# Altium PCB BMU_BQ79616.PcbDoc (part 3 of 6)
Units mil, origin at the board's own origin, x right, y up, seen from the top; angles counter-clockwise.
Board outline 7605 x 4005 mil, 4 copper layers (Top Layer, Layer 1, Layer 2, Bottom Layer), stack 37.446 mil thick; 709 components, 447 nets, 2028 pads, 1862 vias.
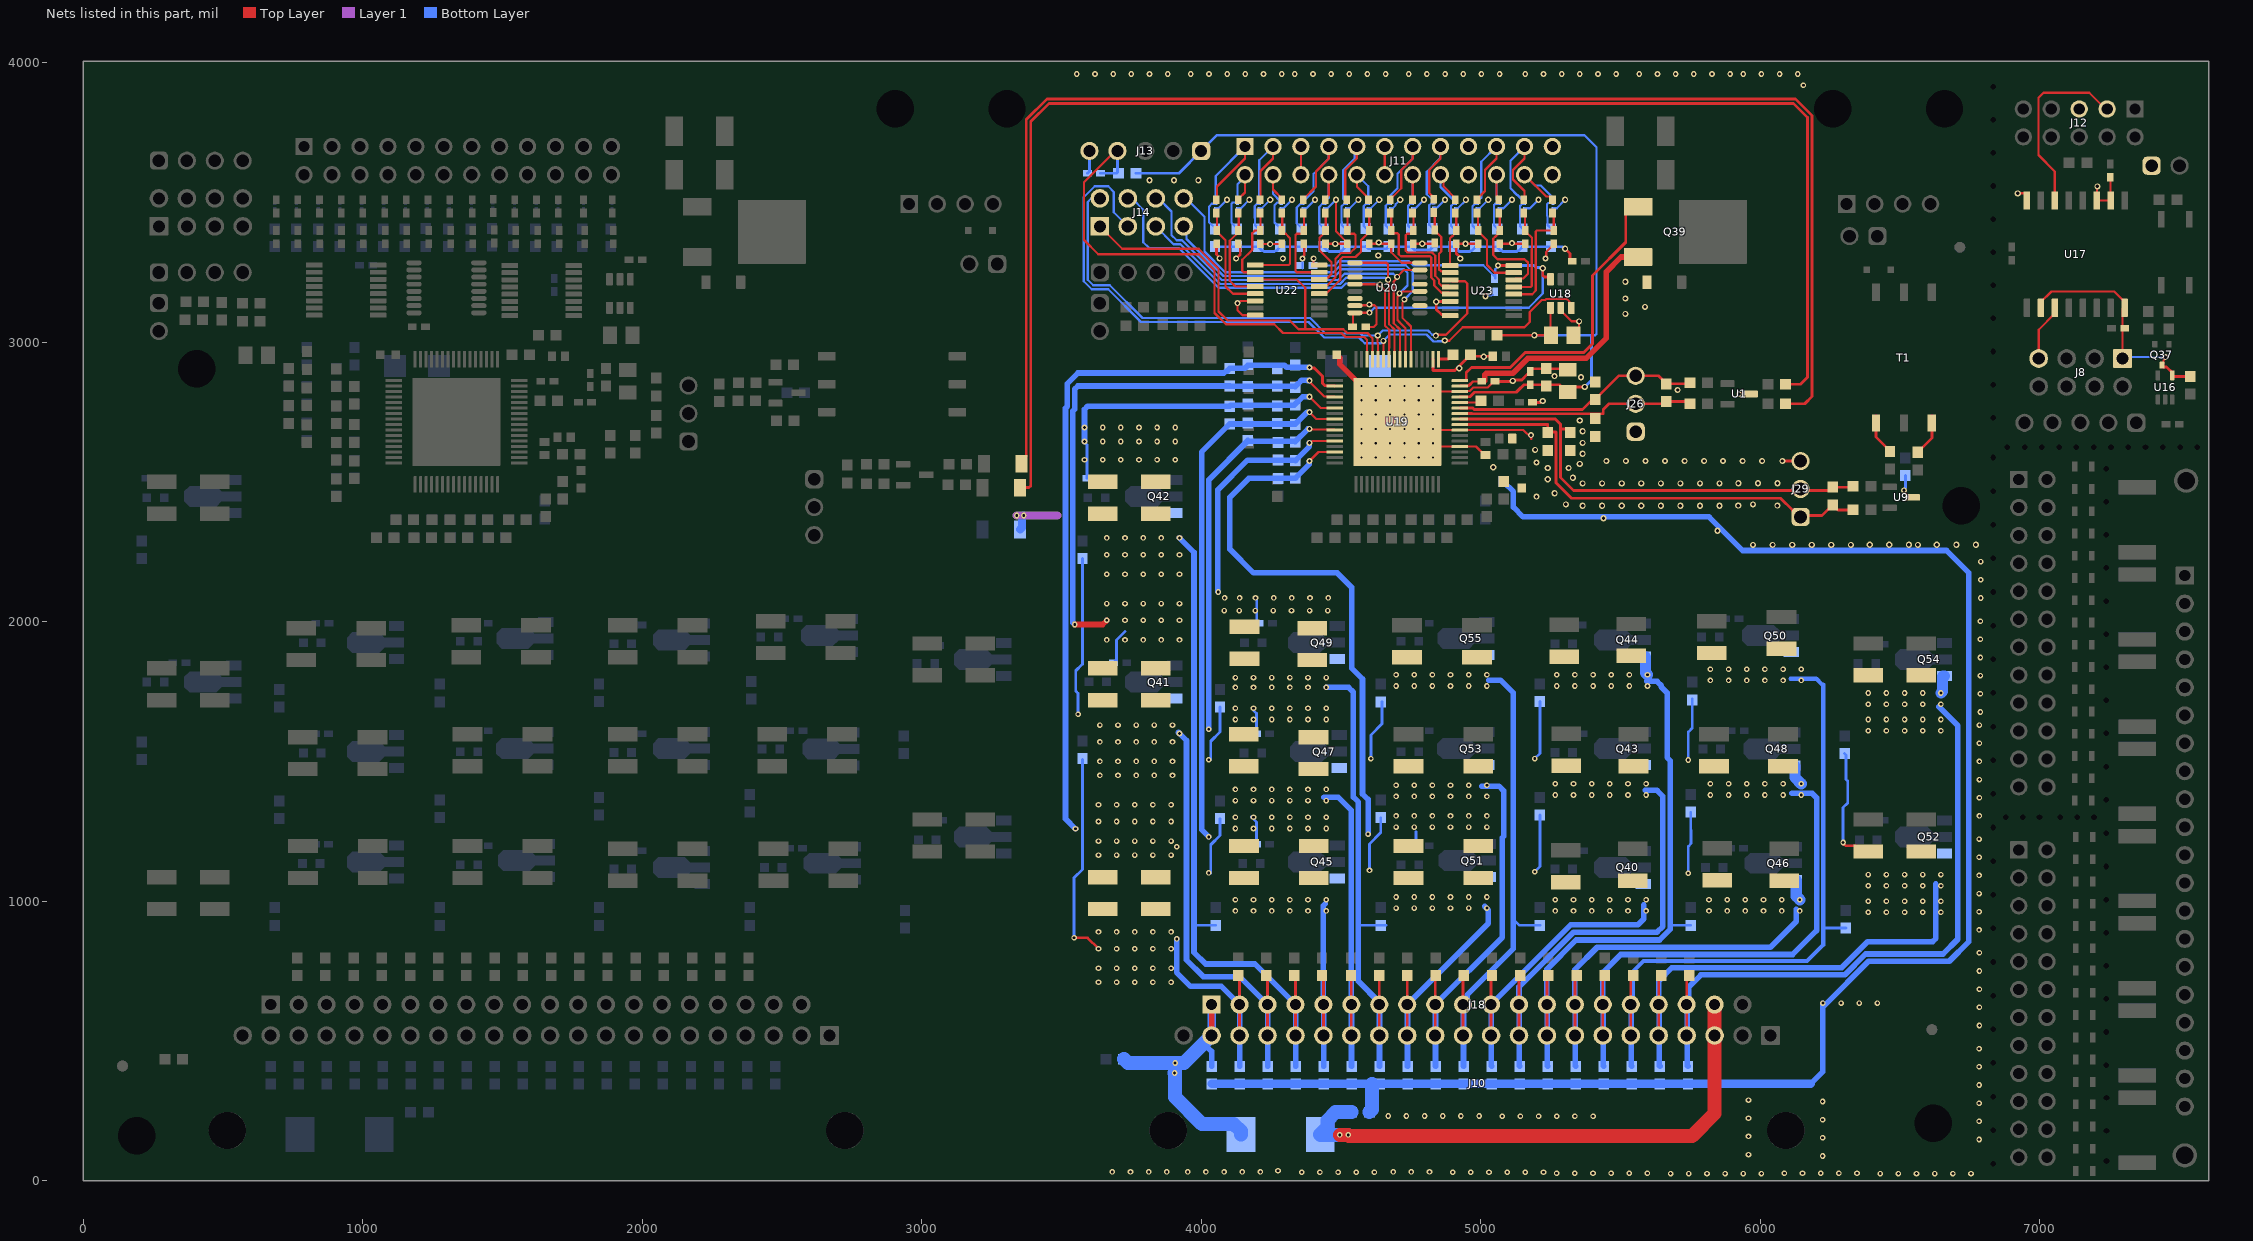
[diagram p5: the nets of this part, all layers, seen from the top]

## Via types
v1: diameter 20, hole 10, Top Layer to Bottom Layer, tented both sides, 1385 vias
v2: diameter 22.01, hole 12.01, Top Layer to Bottom Layer, tented both sides, 405 vias
v3: diameter 19.68, hole 7.87, Top Layer to Bottom Layer, 72 vias

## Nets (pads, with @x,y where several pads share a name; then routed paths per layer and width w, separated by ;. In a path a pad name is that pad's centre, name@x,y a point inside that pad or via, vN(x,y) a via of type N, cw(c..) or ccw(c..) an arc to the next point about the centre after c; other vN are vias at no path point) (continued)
A1_CB10: C212.2 C216.1 R478.1 R480.2 R481.2 U19.14 | length 2085.4
  Top Layer w8: v2(4387.36,2575) 4419.69,2607.32 U19.14@4477.36,2607.32
  Bottom Layer w10: R478.1@4768.74,1198.54 4768.74,1248.62
  Bottom Layer w20: v2(4387.36,2575) 4386.98,2574.62 4386.98,2564.1 4337.36,2514.49 C212.2@4337.36,2513.5 4337.11,2513.25 4272.03,2513.25 4271.77,2512.99 4170.35,2512.99 4102.36,2445 4102.36,2260 4187.36,2175 4486.9,2175 4538.61,2123.28 4538.61,1833.75 4577.36,1795 4577.36,1383.5 4595.86,1365 4597.36,1365 v1(4597.36,1240)
  other v1: 4697.36,1265 4762.36,1265 4827.36,1265 4892.36,1265 4957.36,1265 5022.36,1265 4697.36,1305 4762.36,1305 4827.36,1305 4892.36,1305 4957.36,1305 5022.36,1305
A1_CB11: C208.2 C212.1 R468.1 R470.2 R471.2 U19.12 | length 959.1
  Top Layer w8: v2(4387.36,2640) 4391.15,2640 4397.85,2646.69 U19.12@4477.36,2646.69
  Bottom Layer w10: v1@4194.41,2086.25 4194.41,2083.54 4198.74,2079.21 R468.1@4198.74,1995
  Bottom Layer w20: v1(4060.86,2106.5) 4059.36,2108 4059.36,2472 4165.87,2578.5 4271.77,2578.5 4272.78,2577.5 4336.36,2577.5 C212.1@4337.36,2576.5 4337.36,2577.48 4386.98,2627.1 4386.98,2639.62 v2(4387.36,2640)
  other v1: 4082.36,2040 4136.07,2040 4193.12,2040 4258.12,2040 4323.12,2040 4388.12,2040 4453.12,2040 4083.65,2085.35 4137.36,2085.35 4194.41,2085.35 4259.41,2085.35 4324.41,2085.35 4389.41,2085.35 4454.41,2085.35
A1_CB12: C204.2 C208.1 R87.2 R458.1 R460.2 R461.2 U19.10 | length 1515.8
  Top Layer w8: v2(4387.36,2690) 4389.39,2687.97 4475.46,2687.97 U19.10@4477.36,2686.06
  Bottom Layer w10: v1@4187.36,1685 4187.36,1682.29 4197.52,1672.14 R458.1@4197.52,1598.76
  Bottom Layer w20: v1(4027.36,1615) 4027.36,2508.11 4166.77,2647.52 R87.2@4166.77,2648.5 4169.27,2646 4334.27,2646 C204.2@4336.77,2643.5 4336.77,2644.49 4381.9,2689.62 4386.98,2689.62 v2(4387.36,2690)
  other v1: 4122.36,1650 4187.36,1650 4252.36,1650 4317.36,1650 4382.36,1650 4447.36,1650 4122.36,1690 4187.36,1690 4252.36,1690 4317.36,1690 4382.36,1690 4447.36,1690
A1_CB13: C199.2 C204.1 R87.1 R92.2 R448.1 R449.2 R450.2 U19.8 | length 2041
  Top Layer w8: v2(4387.36,2750) 4411.93,2725.43 U19.8@4477.36,2725.43
  Bottom Layer w10: v1@4179.41,1301.25 4197.52,1283.14 R448.1@4197.52,1203.76
  Bottom Layer w20: v1(4027.36,1230) 4001.36,1256 4001.36,2607.11 4101.77,2707.52 4101.77,2708.5 4102.78,2707.5 4335.77,2707.5 C204.1@4336.77,2706.5 4336.77,2707.48 4378.91,2749.62 4386.98,2749.62 v2(4387.36,2750)
  other v1: 4122.36,1260 4187.36,1260 4252.36,1260 4317.36,1260 4382.36,1260 4447.36,1260 4122.36,1300 4187.36,1300 4252.36,1300 4317.36,1300 4382.36,1300 4447.36,1300
A1_CB14: C194.2 C199.1 R92.1 R150.2 R437.1 R439.2 R440.2 U19.6 | length 1180.8
  Top Layer w8: v2(4387.36,2805) 4427.56,2764.8 U19.6@4477.36,2764.8
  Bottom Layer w10: v1(3582.36,2645) 3582.36,2642.29 3591.69,2632.97 R437.1@3591.69,2513.75
  Bottom Layer w20: v1(3582.36,2645) 3582.36,2759.78 3594.08,2771.5 4101.77,2771.5 4105.28,2775 4333.27,2775 4336.77,2778.5 4336.77,2779.49 4345.47,2788.19 4346.46,2788.19 4362.88,2804.62 4386.98,2804.62 v2(4387.36,2805)
  other v1: 3582.36,2580 3647.36,2580 3712.36,2580 3777.36,2580 3842.36,2580 3907.36,2580 3647.36,2645 3712.36,2645 3777.36,2645 3842.36,2645 3907.36,2645 3582.36,2695 3647.36,2695 3712.36,2695 3777.36,2695 3842.36,2695 3907.36,2695
A1_CB15: C191.2 C194.1 R150.1 R154.2 R428.1 R429.2 R432.2 U19.4 | length 2072.7
  Top Layer w8: v2(4387.36,2863) 4390.04,2860.32 4390.04,2856.31 4440.27,2806.08 4475.46,2806.08 U19.4@4477.36,2804.17
  Top Layer w20: v1(3547.36,1990) 3647.36,1990 v1(3662.36,2005)
  Bottom Layer w10: R428.1@3686.69,1853.75 3692.36,1859.43 3696.3,1859.43 3697.44,1860.57 3697.44,1935.07 3727.36,1965
  Bottom Layer w20: v1(3547.36,1990) 3540.31,1997.05 3540.31,2753.28 3547,2759.97 3547,2831.79 3558.72,2843.5 R154.2@4101.77,2843.5 4102.78,2842.5 4166.77,2842.5 4335.77,2842.5 4336.77,2841.5 4336.77,2842.48 4345.47,2851.18 4346.46,2851.18 4359.89,2864.62 4380.47,2864.62 4381.71,2863.38 4386.98,2863.38 v2(4387.36,2863)
  other v1: 3662.36,1935 3727.36,1935 3792.36,1935 3857.36,1935 3922.36,1935 3727.36,2005 3792.36,2005 3857.36,2005 3922.36,2005 3662.36,2065 3727.36,2065 3792.36,2065 3857.36,2065 3922.36,2065
A1_CB16: C162.1 C191.1 R154.1 R188.2 R420.2 R422.2 U19.2 | length 2641.8
  Top Layer w10: v2(4387.36,2910) 4389.66,2907.7 4404.66,2907.7 4433.87,2878.49 4433.87,2853.49 4442.91,2844.45 4476.46,2844.45 U19.2@4477.36,2843.54
  Bottom Layer w20: v1(3550.31,1258.75) 3514.31,1294.75 3514.31,2764.05 3521,2770.74 3521,2852.2 3558.8,2890 4081.36,2890 4088.17,2896.81 4093.07,2896.81 4101.77,2905.51 R154.1@4101.77,2906.5 4155.75,2906.5 4166.77,2917.52 4166.77,2918.5 4297.36,2918.5 4305.87,2910 v2(4387.36,2910)
  other v1: 3632.36,1165 3697.36,1165 3762.36,1165 3827.36,1165 3892.36,1165 3912.36,1195 3632.36,1215 3697.36,1215 3762.36,1215 3827.36,1215 3892.36,1215 3632.36,1285 3697.36,1285 3762.36,1285 3827.36,1285 3892.36,1285 3632.36,1345 3697.36,1345 3762.36,1345 3827.36,1345 3892.36,1345
A1_CELL0: C103.1 D56.2 J10.3 J18.19 R418.2 | length 2245.1
  Top Layer w50: v1@4496.19,163.41 v1(4526.01,163.41) ; v1@4529.41,160 5757.36,160 5837.36,240 J10.3@5837.36,519.29 J18.19@5837.36,630
  Bottom Layer w20: D56.2@4425.83,165 D56.2@4427.42,163.41 ; J18.19@5837.36,630 5839.86,627.5 5839.86,411.36 C103.1@5842.36,408.86
  Bottom Layer w50: D56.2@4425.83,165 4452.01,191.18 4452.01,215.71 4481.3,245 R418.2@4538.5,245 ; D56.2@4427.42,163.41 v1(4526.01,163.41)
  other v1: 4496.01,163.41
A1_CELL0S: C104.1 J10.4 J18.18 Q54.3 R499.1 R500.1 R501.1 | length 2459.7
  Top Layer w10: J10.4@5737.36,519.29 J18.18@5737.36,630 R501.1@5737.36,723.5
  Bottom Layer w15: J10.4@5737.36,519.29 J10.4@5739.72,521.65
  Bottom Layer w20: C104.1@5742.08,408.86 5739.72,411.22 5739.72,521.65 5739.72,627.64 J18.18@5737.36,630 5744.84,637.48 5744.84,692.48 5788.36,736 6303.06,736 6378.06,811 6654.58,811 6707.36,863.79 6707.36,1628.3 6639.41,1696.25
  Bottom Layer w40: v1(6647.36,1745) 6652.68,1750.31 6652.68,1803.66 6654.96,1805.94 Q54.3@6660.24,1805.94
  other v1: 6387.36,1610 6452.36,1610 6517.36,1610 6582.36,1610 6647.36,1610 6387.36,1650 6452.36,1650 6517.36,1650 6582.36,1650 6647.36,1650 6387.36,1705 6452.36,1705 6517.36,1705 6582.36,1705 6647.36,1705 6387.36,1745 6452.36,1745 6517.36,1745 6582.36,1745
A1_CELL1: C105.1 J10.5 J18.17 Q52.3 R489.1 R492.1 R493.1 R495.1 | length 2180.8
  Top Layer w10: J10.5@5637.36,519.29 J18.17@5637.36,630 R493.1@5637.36,724.44 ; v1(6297.36,1210) 6299.28,1208.09 6299.28,1203.1 6302.36,1203.1 6306.96,1198.5 6341.77,1198.5 R489.1@6367.36,1172.91
  Bottom Layer w10: v1(6297.36,1210) 6297.36,1335 6313.72,1351.36 6313.72,1429.38 6307.36,1435.74 6307.36,1523.5 R495.1@6302.36,1528.5
  Bottom Layer w20: C105.1@5641.81,408.86 5639.58,411.08 5639.58,627.78 J18.17@5637.36,630 5637.36,715 5684.36,762 6292.29,762 6385.29,855 6617.7,855 6629.41,866.72 6629.41,1061.25
  other v1: 6387.36,960 6452.36,960 6517.36,960 6582.36,960 6647.36,960 6387.36,1000 6452.36,1000 6517.36,1000 6582.36,1000 6647.36,1000 6387.36,1055 6452.36,1055 6517.36,1055 6582.36,1055 6647.36,1055 6387.36,1095 6452.36,1095 6517.36,1095 6582.36,1095 6647.36,1095
A1_CELL2: C106.1 J10.6 J18.16 Q50.3 R479.1 R482.1 R483.1 R485.1 | length 2412
  Top Layer w10: J10.6@5537.36,519.29 J18.16@5537.36,630 R483.1@5537.36,725.38
  Bottom Layer w10: 6225.86,910.38 6232.74,903.5 R485.1@6307.36,903.5
  Bottom Layer w15: J10.6@5537.36,519.29 5539.45,521.37 J10.6@5540.06,521.99 ; J18.16@5545.06,630 5545.06,747.7 5582.86,785.5 6167.86,785.5 6225.86,843.5 6225.86,910.38 6225.86,1775 6222.36,1775 6201.12,1796.25 6109.41,1796.25
  Bottom Layer w20: J18.16@5537.36,630 5539.45,627.92 5539.45,521.37 5539.45,410.94 C106.1@5541.53,408.86
  other v1: 5822.36,1790 5887.36,1790 5952.36,1790 6017.36,1790 6082.36,1790 6147.36,1790 5822.36,1830 5887.36,1830 5952.36,1830 6017.36,1830 6082.36,1830 6147.36,1830
A1_CELL3: C107.1 J10.7 J18.15 Q48.3 R469.1 R472.1 R473.1 R475.1 | length 2247.4
  Top Layer w10: J10.7@5437.36,519.29 J18.15@5437.36,630 R473.1@5437.36,726.32
  Bottom Layer w10: v1(5743.36,1505) 5743.36,1606 5757.36,1620 R475.1@5757.36,1723.5
  Bottom Layer w20: C107.1@5441.25,408.86 5439.31,410.8 5439.31,628.06 J18.15@5437.36,630 5437.36,745 5501.36,809 6116.36,809 6202.36,895 6202.36,1370 6186.12,1386.25 6114.41,1386.25
  Bottom Layer w40: Q48.3@6117.17,1485.94 6122.44,1485.94 6124.72,1483.66 6124.72,1442.64 v1(6147.36,1420)
  other v1: 5822.36,1380 5887.36,1380 5952.36,1380 6017.36,1380 6082.36,1380 6147.36,1380 5822.36,1420 5887.36,1420 5952.36,1420 6017.36,1420 6082.36,1420
A1_CELL4: C108.1 J10.8 J18.14 Q46.3 R459.1 R462.1 R463.1 R465.1 | length 1769.2
  Top Layer w10: J10.8@5337.36,519.29 J18.14@5337.36,630 R463.1@5337.36,727.25
  Bottom Layer w10: v1(5743.36,1100) 5743.36,1196 5753.36,1206 5753.36,1254.56 5752.36,1255.56 R465.1@5752.36,1318.5
  Bottom Layer w20: C108.1@5340.97,408.86 5339.17,410.66 5339.17,628.19 J18.14@5337.36,630 5337.36,755 5417.36,835 6037.36,835 6129.41,927.05 6129.41,971.25
  Bottom Layer w40: Q46.3@6122.17,1076.57 6127.44,1076.57 6129.72,1074.28 6129.72,1017.64 v1(6142.36,1005)
  other v1: 5817.36,965 5882.36,965 5947.36,965 6012.36,965 6077.36,965 6142.36,965 5817.36,1005 5882.36,1005 5947.36,1005 6012.36,1005 6077.36,1005
A1_CELL5: C109.1 J10.9 J18.13 Q44.3 R451.1 R452.1 R453.1 R455.1 | length 2151.7
  Top Layer w10: J10.9@5237.36,519.29 J18.13@5237.36,630 R453.1@5237.36,728.19
  Bottom Layer w10: 5678.36,915 5679.86,913.5 R455.1@5752.36,913.5
  Bottom Layer w20: C109.1@5240.69,408.86 5239.03,410.52 5239.03,628.33 J18.13@5237.36,630 5237.36,756.46 5341.9,861 5640.13,861 5678.36,899.23 5678.36,915 5678.36,1503.09 5667.36,1514.09 5667.36,1745.78 5646.36,1766.78 5646.36,1771.78 5631.9,1786.25 5594.41,1786.25
  Bottom Layer w40: Q44.3@5582.17,1875.94 5587.44,1875.94 5589.72,1873.66 5589.72,1817.64 v1(5597.36,1810)
  other v1: 5272.36,1770 5337.36,1770 5402.36,1770 5467.36,1770 5532.36,1770 5597.36,1770 5272.36,1810 5337.36,1810 5402.36,1810 5467.36,1810 5532.36,1810
A1_CELL6: C110.1 J10.10 J18.12 Q43.3 R441.1 R442.1 R443.1 R445.1 | length 1849.9
  Top Layer w10: J10.10@5137.36,519.29 J18.12@5137.36,630 R443.1@5137.36,729.13
  Bottom Layer w10: v1(5193.36,1510) 5212.36,1529 R445.1@5212.36,1715
  Bottom Layer w20: C110.1@5140.42,408.86 5138.89,410.39 5138.89,519.29 5138.89,628.47 J18.12@5137.36,630 5137.36,693.23 5333.13,889 5631.36,889 5652.36,910 5652.36,1375 5631.12,1396.25 5589.41,1396.25
  other v1: 5267.36,1380 5332.36,1380 5397.36,1380 5462.36,1380 5527.36,1380 5592.36,1380 5267.36,1420 5332.36,1420 5397.36,1420 5462.36,1420 5527.36,1420 5592.36,1420
A1_CELL7: C111.1 J10.11 J18.11 Q40.3 R430.1 R431.1 R433.1 R435.1 | length 1367.9
  Top Layer w10: J10.11@5037.36,519.29 J18.11@5037.36,630 R433.1@5037.36,730.07
  Bottom Layer w10: v1(5193.36,1105) 5212.36,1124 R435.1@5212.36,1308.5
  Bottom Layer w20: C111.1@5040.14,408.86 5038.75,410.25 5038.75,628.61 J18.11@5037.36,630 5322.36,915 5562.36,915 5584.41,937.05 5584.41,986.25
  other v1: 5267.36,965 5332.36,965 5397.36,965 5462.36,965 5527.36,965 5592.36,965 5267.36,1005 5332.36,1005 5397.36,1005 5462.36,1005 5527.36,1005 5592.36,1005
A1_CELL8: C112.1 J10.12 J18.10 Q55.3 R419.1 R421.1 R423.1 R425.1 | length 1835
  Top Layer w10: J10.12@4937.36,519.29 J18.10@4937.36,630 R423.1@4937.36,731
  Bottom Layer w10: 5116.36,936 5138.86,913.5 R425.1@5212.36,913.5
  Bottom Layer w20: C112.1@4939.86,408.86 4938.61,410.11 4938.61,519.29 4938.61,628.75 J18.10@4937.36,630 4937.36,642.17 4951.54,656.35 4951.54,664.18 5116.36,829 5116.36,936 5116.36,1746 5071.12,1791.25 5029.41,1791.25
  other v1: 4697.36,1770 4762.36,1770 4827.36,1770 4892.36,1770 4957.36,1770 5022.36,1770 4697.36,1810 4762.36,1810 4827.36,1810 4892.36,1810 4957.36,1810 5022.36,1810
A1_CELL9: C113.1 J10.13 J18.9 Q53.3 R490.1 R491.1 R494.1 R496.1 | length 1607.2
  Top Layer w10: J10.13@4837.36,519.29 J18.9@4837.36,630 R494.1@4837.36,731.94
  Bottom Layer w10: v1(4607.36,1510) 4607.36,1595 4647.36,1635 R496.1@4647.36,1713.5
  Bottom Layer w20: C113.1@4839.58,408.86 4838.47,409.97 4838.47,519.29 4838.47,628.89 J18.9@4837.36,630 5077.36,870 5077.36,1226.72 5082.36,1231.72 5082.36,1395.22 5065.65,1411.94 5003.55,1411.94
  other v1: 4697.36,1375 4762.36,1375 4827.36,1375 4892.36,1375 4957.36,1375 5022.36,1375 4697.36,1415 4762.36,1415 4827.36,1415 4892.36,1415 4957.36,1415 5022.36,1415
A1_CELL10: C114.1 J10.14 J18.8 Q51.3 R480.1 R481.1 R484.1 R486.1 | length 1117.3
  Top Layer w10: J10.14@4737.36,519.29 J18.8@4737.36,630 R484.1@4737.36,732.88
  Bottom Layer w10: v1(4602.36,1110) 4602.36,1205 4642.36,1245 R486.1@4642.36,1298.5
  Bottom Layer w20: C114.1@4739.31,408.86 4738.33,409.83 4738.33,519.29 4738.33,629.03 J18.8@4737.36,630 5027.36,920 5027.36,968.3 5014.41,981.25
  other v1: 4697.36,975 4762.36,975 4827.36,975 4892.36,975 4957.36,975 5022.36,975 4697.36,1015 4762.36,1015 4827.36,1015 4892.36,1015 4957.36,1015 5022.36,1015
A1_CELL11: C115.1 J10.15 J18.7 Q49.3 R470.1 R471.1 R474.1 R476.1 | length 1796.3
  Top Layer w10: J10.15@4637.36,519.29 J18.7@4637.36,630 R474.1@4637.36,733.19
  Bottom Layer w10: 4562.36,913.5 R476.1@4642.36,913.5 4662.36,913.5
  Bottom Layer w20: v1(4447.36,1765) 4527.36,1765 4544.86,1747.5 4544.86,1372.5 4562.36,1355 4562.36,913.5 4562.36,713.36 4637.36,638.36 J18.7@4637.36,630 4638.2,629.17 4638.2,519.29 4638.2,409.69 C115.1@4639.03,408.86
  other v1: 4122.36,1765 4187.36,1765 4252.36,1765 4317.36,1765 4382.36,1765 4122.36,1800 4187.36,1800 4252.36,1800 4317.36,1800 4382.36,1800 4447.36,1800
A1_CELL12: C116.1 J10.16 J18.6 Q47.3 R460.1 R461.1 R464.1 R466.1 | length 1449.2
  Top Layer w10: J10.16@4537.36,519.29 J18.6@4537.36,630 R464.1@4537.36,732.25
  Bottom Layer w10: v1@4034.41,1506.25 4034.41,1572.05 4067.36,1605 R466.1@4067.36,1695
  Bottom Layer w20: 4439.41,1371.25 4491.12,1371.25 4536.36,1326 4536.36,702.59 4537.36,701.59 J18.6@4537.36,630 4538.06,629.31 4538.06,519.29 4538.06,409.55 C116.1@4538.75,408.86
  other v1: 4122.36,1360 4187.36,1360 4252.36,1360 4317.36,1360 4382.36,1360 4447.36,1360 4122.36,1400 4187.36,1400 4252.36,1400 4317.36,1400 4382.36,1400 4447.36,1400 4027.36,1506.25
A1_CELL13: C117.1 J10.17 J18.5 Q45.3 R449.1 R450.1 R454.1 R456.1 | length 1005.2
  Top Layer w10: J10.17@4437.36,519.29 J18.5@4437.36,630 R454.1@4437.36,731.32
  Bottom Layer w10: v1@4034.41,1101.25 4034.41,1202.05 4067.36,1235 R456.1@4067.36,1295
  Bottom Layer w20: C117.1@4438.47,408.86 4437.92,409.41 4437.92,519.29 4437.92,629.44 J18.5@4437.36,630 4437.36,984.19 4444.41,991.25
  other v1: 4122.36,965 4187.36,965 4252.36,965 4317.36,965 4382.36,965 4447.36,965 4122.36,1005 4187.36,1005 4252.36,1005 4317.36,1005 4382.36,1005 4447.36,1005 4027.36,1101.25
A1_CELL14: C118.1 J10.18 J18.4 Q42.3 R439.1 R440.1 R444.1 R446.1 | length 2449.5
  Top Layer w10: J10.18@4337.36,519.29 J18.4@4337.36,630 R444.1@4337.36,730.38
  Bottom Layer w10: 3980.46,913.5 R446.1@4052.36,913.5
  Bottom Layer w20: v1(3922.36,2300) 3974.36,2248 3974.36,913.5 3974.36,816.9 4016.27,775 4192.36,775 J18.4@4337.36,630 4337.78,629.58 4337.78,519.29 4337.78,409.27 C118.1@4338.2,408.86
  other v1: 3662.36,2170 3727.36,2170 3792.36,2170 3857.36,2170 3922.36,2170 3662.36,2240 3727.36,2240 3792.36,2240 3857.36,2240 3922.36,2240 3662.36,2300 3727.36,2300 3792.36,2300 3857.36,2300
A1_CELL15: C119.1 J10.19 J18.3 Q41.3 R429.1 R432.1 R434.1 R436.1 | length 2184.3
  Top Layer w10: J10.19@4237.36,519.29 J18.3@4237.36,630 R434.1@4237.36,729.44
  Bottom Layer w10: v1(3559.31,1668.75) 3559.31,1743.8 3551,1752.11 3551,1824.44 3574.04,1847.49 3575.31,1847.49 R436.1@3575.31,2225.76
  Bottom Layer w20: v1@3918.92,1603.44 3947.36,1575 3947.36,790 4007.36,730 4137.36,730 J18.3@4237.36,630 4237.64,629.72 4237.64,519.29 4237.64,409.14 C119.1@4237.92,408.86
  other v1: 3637.36,1450 3702.36,1450 3767.36,1450 3832.36,1450 3897.36,1450 3637.36,1500 3702.36,1500 3767.36,1500 3832.36,1500 3897.36,1500 3637.36,1570 3702.36,1570 3767.36,1570 3832.36,1570 3897.36,1570 3922.36,1600 3637.36,1630 3702.36,1630 3767.36,1630 3832.36,1630 3897.36,1630
A1_CELL16S: C121.1 J10.20 J18.2 R420.1 R422.1 R424.1 R426.1 | length 1577.1
  Top Layer w10: v1(3545.31,868.75) 3593.61,868.75 v1(3632.36,830) ; J10.20@4137.36,519.29 J18.2@4137.36,630 R424.1@4137.36,728.5
  Bottom Layer w10: v1(3545.31,868.75) 3545.31,1083.75 3575,1113.44 3575,1506.95 R426.1@3575.31,1507.26
  Bottom Layer w20: v1(3912.36,865) 3912.36,745 3962.36,695 4072.36,695 J18.2@4137.36,630 J10.20@4137.36,519.29 4137.5,519.15 4137.5,409 C121.1@4137.64,408.86
  other v1: 3632.36,710 3697.36,710 3762.36,710 3827.36,710 3892.36,710 3632.36,760 3697.36,760 3762.36,760 3827.36,760 3892.36,760 3697.36,830 3762.36,830 3827.36,830 3892.36,830 3632.36,890 3697.36,890 3762.36,890 3827.36,890 3892.36,890
A1_CELL_TOP: C122.1 D56.1 J10.21 J18.1 R417.2 | length 1098.3
  Top Layer w20: J10.21@4037.36,520 J18.1@4037.36,630
  Bottom Layer w20: 4008.85,490.78 4037.36,462.27 C122.1@4037.36,408.86
  Bottom Layer w30: R417.2@3722.36,435 R417.2@3723.35,435 ; J10.21@4037.36,519.29 J18.1@4037.36,630
  Bottom Layer w50: R417.2@3723.35,435 3738.35,420 3906.61,420 v1@3906.61,386.61 ; v1(3905,385) v1@3906.61,386.61 ; v1(3906.61,420.71) 3938.78,420.71 4008.85,490.78 J10.21@4037.36,519.29 ; D56.1@4142.36,165 4142.36,176.81 4116.18,202.99 4002.01,202.99 3906.61,298.39 v1@3906.61,386.61
A1_COMHN: C45.1 J26.2 R74.1 R78.1 U19.42 | length 853.3
  Top Layer w10: U19.42@4926.18,2745.12 4969.18,2745.12 4970.3,2744 5438.54,2744 5438.54,2758.54 5460,2780 J26.2@5555,2780 5656.5,2780 R74.1@5665,2788.5 5740,2788.5 R78.1@5748.5,2780
A1_COMHP: C44.1 J26.3 R72.1 R74.2 U19.43 | length 866.4
  Top Layer w10: U19.43@4926.18,2764.8 4972.12,2764.8 4976.92,2760 5365,2760 C44.1@5391.5,2786.5 ; C44.1@5410,2795 5415,2790 5420,2795 5420,2805.98 5494.02,2880 J26.3@5545,2880 ; J26.3@5555,2880 5637.48,2880 5665,2852.48 R74.2@5665,2851.5 5745,2851.5 R72.1@5748.5,2855
A1_COMLN: C49.1 J29.2 R81.2 R85.2 U19.41 | length 1670.3
  Top Layer w10: U19.41@4926.18,2725.43 5267.08,2725.43 5286,2706.52 5286,2690 ; C49.1@5320,2676.5 5306.5,2690 5286,2690 ; R81.2@6333.5,2485 6330,2481.5 R85.2@6260,2481.5 6248.5,2470 5332.36,2470 5286,2516.36 5286,2690
A1_COMLP: C48.1 J29.1 R85.1 R89.2 U19.40 | length 1699.5
  Top Layer w10: U19.40@4926.18,2705.75 5240,2705.75 C48.1@5240,2676.5 5242.5,2679 5270,2679 5270,2497.36 5325.36,2442 6073,2442 6115.47,2399.53 6120.47,2399.53 6134.92,2385.08 6134.92,2380.08 6221.57,2380.08 6245.31,2403.82 6246.3,2403.82 R85.1@6260,2417.52 ; R85.1@6260,2418.5 R85.1@6260,2417.52 ; R89.2@6338.5,2400 6278.5,2400 6274.69,2403.82 6273.7,2403.82 R85.1@6260,2417.52
A1_COMMH_N_OPT: C41.2 R77.2 | length 5200.1
  Top Layer w10: C41.2@3361.93,2579.84 3373.58,2591.5 3373.58,3796.21 3448.37,3871 6126.63,3871 6185.57,3812.05 6185.57,3811.15 6186,3810.72 6186,2806 6160,2780 R77.2@6091.5,2780
A1_COMMH_P_OPT: C40.2 R71.2 | length 5191.1
  Top Layer w10: C40.2@3351.93,2480 3384.14,2480 3390,2485.86 3390,3790 3455,3855 6120,3855 6170,3805 6170,2875 6145,2850 R71.2@6091.5,2850
A1_COMML_N_OPT: R80.1 T1.1 | length 147
  Top Layer w10: T1.1@6415,2736.24 T1.1@6415,2711.24 6415,2660.98 6465,2610.98 R80.1@6465,2610
A1_COMML_P_OPT: R88.1 T1.3 | length 147.9
  Top Layer w10: R88.1@6565,2606.5 6565,2607.48 6615,2657.48 T1.3@6615,2711.24 ; T1.3@6610.62,2715.62 6615,2720 T1.3@6615,2736.24
A1_CVDD: C155.1 C166.1 C169.1 C170.2 J13.1 R143.1 R146.1 U18.1 U19.45 | length 3559.8
  Top Layer w8: R143.1@5058.86,3025 v2(5192.36,3025) 5247.56,3025 5249.96,3027.4 U18.1@5249.96,3123.37 ; C166.1@5319.36,2821.69 C166.1@5324.36,2816.69
  Top Layer w10: U19.45@4926.18,2804.17 4927.09,2805.08 4962,2805.08 4978.11,2821.18 5127.67,2821.18 5136.49,2830 5154.24,2847.76 C170.2@5177.36,2847.76 5283.11,2847.76 5305.86,2825 C166.1@5312.36,2825 ; C166.1@5335.36,2840 v2@5372.51,2840
  Bottom Layer w8: J13.1@4000,3685 4055,3740 4055,3741.3 5372.01,3741.3 5414.84,3698.47 5414.84,3029.69 5410.16,3025 v2(5192.36,3025) v2@5192.36,3021.21
  Bottom Layer w10: R146.1@3766.5,3605 3920,3605 J13.1@4000,3685 ; v2(5372.79,2840.28) 5396.87,2864.35 5396.87,3023.85
A1_CVDD_CO: C2.1 J8.1 Q37.3 R196.2 U16.4 U17.10 U17.16 | length 866.7
  Top Layer w8: U17.10@7004.95,3123.57 7004.95,3144.24 7042.67,3181.97 7267.22,3181.97 7304.95,3144.24 U17.16@7304.95,3123.57 ; J8.1@7297.24,2941.97 U17.16@7297.24,3119.97 ; Q37.3@7438.24,2918.57 7443.49,2923.82 7443.49,2935.43 7451.24,2943.18 v2(7451.24,2946.97)
  Top Layer w10: Q37.3@7438.24,2918.57 7438.24,2916.01 7442.49,2911.76 7454.7,2911.76 7475,2891.46 U16.4@7475,2881.61 7475,2880.87 7477.87,2877.99 R196.2@7540,2877.99
  Bottom Layer w8: J8.1@7297.24,2941.97 7302.24,2946.97 v2(7451.24,2946.97)
A1_CVDD_SW: C161.2 C171.1 C172.1 U18.6 U20.16 U22.16 U23.16 | length 1930.2
  Top Layer w8: v2(4402.36,3300) 4402.36,3281.04 4407.22,3276.18 U22.16@4421.71,3276.18 ; C161.2@4543.74,3055 4543.74,3100.94 4548.23,3105.43 U20.16@4550.22,3105.43 4550.51,3105.72 4602.08,3105.72 v2(4602.36,3106) ; 5237.5,3233.48 U18.6@5249.96,3221.02
  Top Layer w10: v2(5062.36,3275) 5062.58,3274.78 5121.32,3274.78 U23.16@5121.54,3274.57 ; v2(5222.36,3265) 5222.36,3239.34 5228.22,3233.48 5237.5,3233.48 ; U18.6@5249.96,3221.02 U18.6@5249.96,3225.73
  Bottom Layer w8: v2(4402.36,3300) 4402.36,3275 4477.76,3275 4492.47,3289.71 4743.84,3289.71 4757.84,3275.71 5009.22,3275.71 C172.1@5052.36,3232.56 ; v2(4602.36,3106) 4620.35,3124 5171.85,3124 5222.36,3174.51 v2(5222.36,3265) ; C172.1@5052.36,3228.62 C172.1@5052.36,3232.56 ; v2(5062.36,3275) 5062.36,3271.21 5052.36,3261.21 C172.1@5052.36,3232.56
  Bottom Layer w10: v2(5062.36,3275) 5191.36,3275 5199.06,3267.3 5220.06,3267.3 v2(5222.36,3265)
A1_DVDD: C167.2 U19.49 | length 57.7
  Top Layer w10: U19.49@4849.41,2940 4884.88,2940 4899.88,2955 C167.2@4900.87,2955
A1_EE_NCS: U20.14
A1_EE_SCK: U20.2
A1_EE_SI: U20.5
A1_EE_SO: U20.11
A1_GND: C15.1 C44.2 C45.2 C46.2 C48.2 C49.2 C103.2 C104.2 C105.2 C106.2 C107.2 C108.2 C109.2 C110.2 C111.2 C112.2 C113.2 C114.2 C115.2 C116.2 C117.2 C118.2 C119.2 C121.2 C122.2 C153.2 C154.1 C155.2 C158.2 C159.1 C160.1 C161.1 C163.2 C165.1 C166.2 C167.1 C168.1 C169.2 C170.1 C171.2 C172.2 C173.2 C174.2 C175.2 C176.2 C177.2 C178.2 C180.2 C181.2 C182.2 C183.2 C184.2 C185.2 C186.2 C187.2 C188.2 C189.2 C222.2 C223.2 D3.2 D12.2 D13.2 D14.2 D15.2 D18.2 D19.2 D20.2 D21.2 D24.2 D25.2 D26.2 D27.2 D30.2 D31.2 D32.2 D33.2 D45.1 J11.5 J11.6 J11.11 J11.12 J11.17 J11.18 J11.23 J11.24 J13.5 J26.1 J29.3 R418.1 U1.3 U9.3 U18.2 U19.36 U19.39 U19.46 U19.50 U19.65 U20.8 U20.15 U22.6 U22.8 U23.6 U23.8 | length 11364.9
  Top Layer w8: U22.8@4193.36,3097.05 4147.95,3097.05 4130,3115 v2(4130,3140) 4133.79,3140 4142.02,3148.23 U22.6@4193.36,3148.23 ; C178.2@4210.99,3352.76 4212.37,3351.38 v2(4246.72,3351.38) C181.2@4288.99,3351.38 ; J11.6@4356.77,3599.61 J11.5@4356.77,3700.39 ; v2(4362.36,3300) 4362.36,3303.79 4368.77,3310.2 C183.2@4368.77,3352.76 ; C185.2@4444.99,3352.76 4445.43,3352.32 v2(4479.73,3352.32) 4522.05,3352.32 C187.2@4522.99,3351.38 ; v2(4482.36,3510) 4482.36,3397.32 4522.99,3356.69 C187.2@4522.99,3352.76 ; U20.15@4550.22,3131.02 4552.08,3132.88 v2@4599.54,3132.88 ; C161.1@4590.98,3055 4617.36,3055 4627.36,3065 4627.36,3125 4620.04,3132.32 v2@4608.83,3132.32 ; C189.2@4600.99,3352.76 v2@4635.42,3352.76 ; v2(4635.42,3357) v2@4635.42,3352.76 ; J11.12@4656.77,3599.61 J11.11@4656.77,3700.39 ; U20.8@4782.5,3284.57 4782.07,3285 4717.56,3285 4679.99,3322.57 C173.2@4679.99,3352.76 v2@4635.42,3352.76 ; v3(4829.72,2638.82) 4841.54,2627.01 U19.36@4926.18,2627.01 4983.78,2627.01 5014.41,2596.38 C165.1@5017.36,2596.38 ; v3(4829.72,2690) 4833.66,2686.06 U19.39@4926.18,2686.06 5152.87,2686.06 5180.98,2657.95 5180.98,2655 ; v3(4829.72,2843.54) 4849.41,2823.86 U19.46@4926.18,2823.86 4928.09,2825.76 4961.47,2825.76 4973.9,2838.19 5025.24,2838.19 5047.05,2860 C160.1@5050.98,2860 ; C180.2@4912.99,3352.76 v2(4945.76,3352.76) C182.2@4990.99,3352.76 ; C184.2@5068.99,3352.76 C186.2@5159.99,3352.76 ; v2(5232.36,3300) 5235.04,3302.68 5235.04,3322.83 5261.04,3348.82 C188.2@5261.04,3352.76 ; U18.2@5286.66,3108.12 U18.2@5287.36,3108.82 ; U18.2@5287.36,3113.52 5301.95,3098.93 ; 5301.95,3098.33 5325.28,3075 v2(5352.36,3075) 5352.36,3045 C155.2@5332.36,3025 C155.2@5332.36,3031.5
  Top Layer w10: C174.2@4054.99,3354.72 C174.2@4054.99,3352.76 4054.99,3314.52 4065.87,3303.64 v2(4065.87,3300.39) ; v2(4125,3300) 4139.7,3314.7 C176.2@4139.7,3347.83 ; C163.2@4485.36,2955 C163.2@4495.36,2945 ; C175.2@4758.99,3352.76 v2(4791.34,3352.76) 4833.34,3352.76 C177.2@4835.58,3355 ; 4829.72,2908.93 4829.72,2899.47 4907.35,2899.47 4962.87,2955 C167.1@4963.86,2955 C167.1@4968.86,2950 ; U19.50@4829.72,2940 4830.63,2939.09 4830.63,2908.93 ; U23.8@4890.83,3095.43 4886.97,3099.29 4859.76,3099.29 4841.07,3117.98 v2(4841.07,3145) 4841.87,3145.81 4890.02,3145.81 U23.6@4890.83,3146.61 ; C180.2@4912.99,3352.76 4912.99,3317.62 4927.36,3303.25 v2(4927.36,3300) ; C167.1@4967.87,2950 C167.1@4968.86,2950 ; C158.2@5043.74,2950 C167.1@4968.86,2950 ; C160.1@5050.98,2860 5113.02,2860 v2(5115.02,2862) ; v2@5115,2865 5147.36,2865 5166.61,2884.25 5170.55,2884.25 5177.36,2891.06 C170.1@5177.36,2895 ; C170.1@5177.36,2898.19 5184.17,2905 C166.2@5312.36,2905 ; C159.1@5185.98,2785 5214.11,2785 5219.11,2790 v2(5222.36,2790) ; v2(5925,2815) U1.3@5966.34,2815 ; v2@6077.7,2572.7 v2(6080,2575) J29.3@6145,2575 ; v2@6517.3,2460.26 6532.56,2445 U9.3@6546.34,2445
  Top Layer w20: C163.2@4495.36,2945 4495.36,2922 v3(4573.82,2843.54)
  Layer 1 w30: v1(3340,2380) v1(3365,2380) 3485,2380
  Bottom Layer w8: D13.2@4051.77,3475.32 4051.77,3477.78 4053.68,3479.68 4062.04,3479.68 v2(4092.36,3510) ; D15.2@4130.14,3475.39 4130.14,3477.85 4132.05,3479.75 4142.11,3479.75 v2(4172.36,3510) ; D19.2@4208.14,3475.39 4208.14,3477.85 4210.05,3479.76 4217.12,3479.76 v2(4247.36,3510) ; D21.2@4286.14,3475.39 4286.14,3477.85 4288.05,3479.76 4294.76,3479.76 v2(4325,3510) ; C171.2@4362.36,3265 v2(4362.36,3300) ; D25.2@4364.14,3475.39 4364.14,3477.85 4366.05,3479.76 4377.12,3479.76 v2(4407.36,3510) ; D27.2@4442.15,3475.4 4442.15,3477.86 4444.05,3479.76 4452.13,3479.76 v2(4482.36,3510) ; D31.2@4520.14,3475.39 4520.14,3477.85 4522.05,3479.76 4532.12,3479.76 v2(4562.36,3510) ; D33.2@4598.14,3475.4 4598.14,3477.86 4600.05,3479.77 4607.13,3479.77 v2(4637.36,3510) ; D12.2@4677.14,3475.38 4677.14,3477.84 4679.05,3479.75 4685.32,3479.75 4695.8,3490.23 4695.8,3494.03 4711.76,3510 v2(4712.36,3510) ; D14.2@4756.14,3475.39 4756.14,3477.85 4758.05,3479.75 4767.12,3479.75 v2(4797.36,3510) ; D18.2@4832.73,3477.7 4832.73,3480.16 4834.64,3482.06 4844.43,3482.06 v2(4872.36,3510) ; D20.2@4910.14,3475.39 4910.14,3477.85 4912.05,3479.76 4918.32,3479.76 4947.36,3508.81 v2(4947.36,3510) ; D24.2@4988.14,3475.39 4988.14,3477.85 4990.05,3479.76 4997.12,3479.76 v2(5027.36,3510) ; v2@5020.04,3167.68 C172.2@5038.66,3167.68 ; C172.2@5040.61,3169.63 C172.2@5044.55,3169.63 ; D26.2@5066.14,3475.4 5066.14,3477.86 5068.05,3479.77 5082.13,3479.77 v2(5112.36,3510) ; D30.2@5157.14,3475.39 5157.14,3477.85 5159.05,3479.76 5177.12,3479.76 v2(5207.36,3510) ; D32.2@5258.77,3475.4 5258.77,3477.86 5260.68,3479.76 5272.12,3479.76 v2(5302.36,3510)
  Bottom Layer w10: C15.1@3592.76,3605 3593.19,3605 3600,3611.81 J13.5@3600,3685 ; v2(6515,2470) 6515,2473.25 6520,2478.25 C46.2@6520,2523.5
  Bottom Layer w20: C223.2@5082.36,2501.5 5082.36,2500.51 5117.36,2465.51 5117.36,2410 5152.36,2375 5817.36,2375 5937.36,2255 ; 6045,2255 5937.36,2255 ; 6180.87,345.87 6225,390 v1(6225,635) ; v1@6231.92,628.08 6388.83,785 6677.06,785 6747.36,855.3 6747.36,2175 6667.36,2255 5937.36,2255
  Bottom Layer w30: C153.2@3351.93,2330 3358.58,2336.65 3358.58,2373.58 v1(3365,2380) ; C122.2@4037.36,345.87 C121.2@4137.36,345.87 C119.2@4237.92,345.87 C118.2@4338.2,345.87 C117.2@4438.47,345.87 C116.2@4538.75,345.87 4610.49,345.87 C115.2@4639.03,345.87 C114.2@4739.31,345.87 C113.2@4839.58,345.87 C112.2@4939.86,345.87 C111.2@5040.14,345.87 C110.2@5140.42,345.87 C109.2@5240.69,345.87 C108.2@5340.97,345.87 C107.2@5441.25,345.87 C106.2@5541.53,345.87 C105.2@5641.81,345.87 C104.2@5742.08,345.87 C103.2@5842.36,345.87 6180.87,345.87
  Bottom Layer w50: R418.1@4601.5,245 4610.49,253.99 4610.49,345.87
  other v1: 5680,25 5745,25 5810,25 5875,25 5940,25 6005,25 6430,25 6495,25 6560,25 6625,25 6690,25 6755,25 5272.05,26.25 5337.05,26.25 5402.05,26.25 5467.05,26.25 5532.05,26.25 5597.05,26.25 6087.05,26.25 6152.05,26.25 6217.05,26.25 6282.05,26.25 6347.05,26.25 4360,30 4425,30 4490,30 4555,30 4620,30 4900,30 4965,30 5030,30 5095,30 5160,30 5225,30 3682.05,31.25 3747.05,31.25 3812.05,31.25 3877.05,31.25 3952.05,31.25 4017.05,31.25 4082.05,31.25 4147.05,31.25 4212.05,31.25 4687.05,31.25 4752.05,31.25 4817.05,31.25 4275,35 6223.75,88 5958.75,93 6783.75,147.05 6223.75,153 5958.75,158 6783.75,212.05 6223.75,218 5958.75,223 5077.36,230 5142.36,230 5207.36,230 5272.36,230 5337.36,230 5402.36,230 4669.41,231.25 4734.41,231.25 4799.41,231.25 4864.41,231.25 4929.41,231.25 4994.41,231.25 6783.75,277.05 6223.75,283 5958.75,288 6783.75,342.05 6783.75,407.05 6783.75,472.05 6785,555 6785,620 6290,635 6355,635 6420,635 6785,685 6785,750 6785,815 6783.75,897.05 6783.75,962.05 6783.75,1027.05 6783.75,1092.05 6783.75,1157.05 6783.75,1222.05 6785,1305 6785,1370 6785,1435 6785,1500 6785,1565 6785,1630 6788.75,1677.05 6788.75,1742.05 6788.75,1807.05 6788.75,1872.05 6788.75,1937.05 6788.75,2002.05 6790,2085 6790,2150 6790,2215 6155,3920 3555,3960 3620,3960 3685,3960 3750,3960 3815,3960 3880,3960 3962.95,3960 4027.95,3960 4092.95,3960 4157.95,3960 4222.95,3960 4287.95,3960 4335,3960 4400,3960 4465,3960 4530,3960 4595,3960 4660,3960 4742.95,3960 4807.95,3960 4872.95,3960 4937.95,3960 5002.95,3960 5067.95,3960 5160,3960 5225,3960 5290,3960 5355,3960 5420,3960 5485,3960 5567.95,3960 5632.95,3960 5697.95,3960 5762.95,3960 5827.95,3960 5892.95,3960 5940,3960 6005,3960 6070,3960 6135,3960
  other v2: 5975,2275 6045,2275 6115,2275 6185,2275 6255,2275 6325,2275 6392.48,2275.32 6462.48,2275.32 6532.48,2275.32 6565,2275 6632.48,2275.32 6702.48,2275.32 6772.48,2275.32 5847.8,2325.41 5439.95,2370.04 5365,2415 5435,2415 5505,2415 5575,2415 5645,2415 5715,2415 5785,2415 5855,2415 5922.08,2415.6 6062.08,2415.6 5305,2420 5975,2420 5200.08,2447.76 5265,2460 5365,2495 5435,2495 5505,2495 5575,2495 5645,2495 5715,2495 5785,2495 5855,2495 5922.48,2495.32 5992.48,2495.32 6062.48,2495.32 5240,2510 5330,2515 5240,2550 5315,2550 5045.08,2552.76 5355,2565 5200,2570 5450,2575 5520,2575 5590,2575 5660,2575 5730,2575 5800,2575 5867.48,2575.32 5937.48,2575.32 6007.48,2575.32 5365,2601.38 5195,2615 5365,2640 5180.08,2667.76 5365,2681.38 5355,2720 5705,2829.49 5359.36,2875 5264.17,2878.78 4923.66,2907.13 5011,2948.3 5518.04,3101.69 5588.04,3126.69 4602.01,3135.35 5518.04,3156.69 5017.36,3165 5518.04,3216.69 4292.36,3300 4633.56,3310.71 5112.36,3355 3815,3580 3902.5,3580 3990,3580
  other v3: 4573.82,2587.64 4625,2587.64 4676.18,2587.64 4727.36,2587.64 4778.54,2587.64 4829.72,2587.64 4573.82,2638.82 4625,2638.82 4676.18,2638.82 4727.36,2638.82 4778.54,2638.82 4573.82,2690 4625,2690 4676.18,2690 4727.36,2690 4778.54,2690 4573.82,2741.18 4625,2741.18 4676.18,2741.18 4727.36,2741.18 4778.54,2741.18 4829.72,2741.18 4573.82,2792.36 4625,2792.36 4676.18,2792.36 4727.36,2792.36 4778.54,2792.36 4829.72,2792.36 4625,2843.54 4676.18,2843.54 4727.36,2843.54 4778.54,2843.54
A1_GND_ISO: C4.1 J5.1 J12.5 U17.2 U17.3 U17.8 | length 234.1
  Top Layer w8: v2(6922.24,3532.97) 6947.13,3532.97 6954.95,3525.16 U17.8@6954.95,3507.43 ; v2(7207.24,3557.97) 7206.09,3556.82 7206.09,3508.57 U17.3@7204.95,3507.43 7247.13,3507.43 7254.09,3514.39 7254.09,3590.11 C4.1@7253.24,3590.97
A1_GPIO1: J14.1 U19.61 U22.3 | length 1645.7
  Top Layer w8: J14.1@3637.36,3415 3717.36,3335 3991,3335 4062.36,3263.64 4062.36,3110.44 4094.61,3078.19 4316.92,3078.19 4348.11,3047 4372.36,3047 ; U22.3@4193.36,3225 4342.36,3225 4372.36,3195 4372.36,3047 ; U19.61@4613.19,2940 4613.19,3013.45 4610.85,3015.79 4610.85,3017.39 4595.05,3033.19 4521.88,3033.19 4508.07,3047 4372.36,3047
A1_GPIO2: J14.2 U19.60 U23.3 | length 2022.5
  Top Layer w8: v2(4631.85,3024.49) 4630.91,3023.54 4630.91,2996.99 4632.87,2995.02 4632.87,2960.4 U19.60@4632.62,2960.15 ; v2(4840,3024) 4842.68,3026.68 4862.47,3026.68 4862.99,3027.19 4876.33,3027.19 4952.36,3103.22 4952.36,3210 4943.83,3218.53 4898.05,3218.53 U23.3@4893.19,3223.39
  Bottom Layer w8: J14.2@3606.52,3515 3593.9,3502.38 3593.9,3223.88 3613.77,3204 3673.16,3204 3790.16,3087 4389.87,3087 4445.87,3031 4570.16,3031 4577.16,3024 4631.36,3024 v2(4631.85,3024.49) 4649.37,3042 4811.99,3042 4827.31,3026.68 4837.32,3026.68 v2(4840,3024)
A1_GPIO3: J14.3 U18.3 U19.59 | length 2623.4
  Top Layer w8: v2(4651.91,3004.94) 4652.23,3004.62 4652.23,2940.32 U19.59@4652.56,2940 ; v2(4871.88,3006.19) 4872.8,3005.26 4887.63,3005.26 4936.16,3053.8 5157.36,3053.8 5176.16,3072.6 5176.16,3108.8 5218.45,3151.09 5231.25,3151.09 5235.18,3155.02 5308.34,3155.02 5316.95,3146.4 5316.95,3116.63 U18.3@5324.76,3108.82
  Bottom Layer w8: J14.3@3737.36,3415 3687.36,3465 3687.36,3538.17 3667.07,3558.46 3619.36,3558.46 3579.9,3519 3579.9,3218.08 3607.97,3190 3667.36,3190 3784.36,3073 4384.07,3073 4440.07,3017 4564.36,3017 4569.68,3011.68 4570.48,3011.68 4585.18,2996.99 4643.37,2996.99 4651.32,3004.94 v2(4651.91,3004.94) ; v2@4651.91,3005 4674.91,3028 4806.19,3028 4831.2,3002.99 4844.87,3002.99 4845.39,3003.51 4869.2,3003.51 v2(4871.88,3006.19)
A1_GPIO4: J14.4 U19.58 U20.12 | length 1481.5
  Top Layer w8: U20.12@4550.22,3207.8 4550.43,3207.59 4639.48,3207.59 v2(4639.69,3207.38) 4639.69,3204.53 4657.36,3186.86 4657.36,3060.2 4672.91,3044.65 4672.91,2979.86 4672.24,2979.19 U19.58@4672.24,2940
  Bottom Layer w8: J14.4@3737.36,3515 3752.36,3515 3793.01,3474.36 3793.01,3357.89 3813.65,3337.25 3920.12,3337.25 4062.36,3195 4502.36,3195 4517.36,3210 4637.07,3210 v2(4639.69,3207.38)
A1_GPIO5: J14.5 U19.57 U20.9 | length 1396.5
  Top Layer w8: U20.9@4550.22,3284.57 4662.8,3284.57 4668.81,3278.55 v2(4668.81,3223.89) ; v2@4672.59,3223.89 4672.59,3064.77 4691.93,3045.43 U19.57@4691.93,2940
  Bottom Layer w8: J14.5@3837.36,3415 3901.12,3351.25 3925.92,3351.25 4068.16,3209 4496.36,3209 4518.36,3231 4657.91,3231 4665.02,3223.89 v2(4668.81,3223.89)
A1_GPIO6: J14.6 U19.56 U20.7 | length 1449
  Top Layer w8: U19.56@4711.61,2940 4711.36,2940.26 4711.36,3046 4688.94,3068.43 4688.94,3217.89 4701.26,3230.21 4701.26,3235 4725.23,3258.98 U20.7@4782.5,3258.98
  Bottom Layer w8: J14.6@3837.36,3515 3847.36,3515 3893.9,3468.46 3893.9,3383.46 3912.12,3365.25 3931.71,3365.25 4073.96,3223 4490.56,3223 4512.56,3245 4687.47,3245 4698.47,3234 v2(4701.26,3234)
A1_GPIO7: J14.7 U19.55 U20.4 | length 1303.1
  Top Layer w8: U19.55@4731.3,2940 4731.3,3050.66 4709.07,3072.89 4709.07,3073.29 4702.94,3079.43 4702.94,3164.21 4709.94,3171.21 v2(4709.94,3175) 4713.73,3175 4720.94,3182.2 U20.4@4763.5,3182.2
  Bottom Layer w8: J14.7@3937.36,3415 3947.22,3405.14 3947.22,3369.54 4079.76,3237 4479.36,3237 4503.36,3261 4614.16,3261 4614.86,3261.71 4725.66,3261.71 4738.37,3249 4738.37,3203.43 v2(4709.94,3175)
A1_GPIO8: J14.8 U19.54 | length 1361.5
  Top Layer w8: v2(4727.21,3152.95) 4727.21,3149.16 4720,3141.95 4720,3087.56 4750.98,3056.58 U19.54@4750.98,2940
  Bottom Layer w8: J14.8@3937.36,3515 3945.79,3515 4011.96,3448.83 4011.96,3324.6 4085.56,3251 4473.56,3251 4498.27,3275.71 4731.97,3275.71 4757.36,3250.31 4757.36,3183.61 4727.21,3153.45 v2(4727.21,3152.95)
A1_LDOIN: C160.2 Q39.3 U19.47 | length 1004.3
  Top Layer w8: U19.47@4926.18,2843.54 4927.09,2844.45 4928.09,2845.45 4957.81,2845.45 4960.59,2848.23 4961.03,2848.23 ; 4971.09,2858.29 4972.8,2860 C160.2@5003.74,2860
  Top Layer w10: U19.47@4927.09,2844.45 4957.25,2844.45 4961.03,2848.23 4971.09,2858.29
  Top Layer w20: C160.2@5014.49,2861.81 5014.49,2883.14 5020.35,2889 5114.86,2889 5168.56,2942.69 5377.68,2942.69 5449.86,3014.87 5449.86,3252.5 5502.6,3305.24 Q39.3@5563.5,3305.24
A1_NEG5V: R155.1 U19.44 | length 76
  Top Layer w8: U19.44@4926.18,2784.49 4994.37,2784.49 R155.1@4999.88,2790
A1_NF_J_CO: J8.7 U17.11 | length 205.5
  Top Layer w8: J8.7@6997.24,2941.97 6997.24,3045.19 7054.95,3102.9 U17.11@7054.95,3123.57
A1_NFAULT: C15.2 J13.4 R146.2 U19.62 | length 1829.8
  Top Layer w8: J13.4@3700,3685 3693,3685 3581,3573 3581,3366 3631.97,3315.03 3991.17,3315.03 4048,3258.2 4048,3105 4088.81,3064.19 4261.81,3064.19 4293,3033 4502.27,3033 4516.08,3019.19 4583.81,3019.19 4593.5,3009.5 U19.62@4593.5,2940
  Bottom Layer w10: C15.2@3640,3605 3696.5,3605 3700,3608.5 J13.4@3700,3685
A1_NFAULT_C: J12.3 U17.6 | length 664.7
  Top Layer w8: U17.6@7054.95,3507.43 7054.95,3611.26 6996.33,3669.87 6996.33,3875.06 7014.24,3892.97 7178.24,3892.97 J12.3@7237.24,3833.97
A1_NPNB: Q39.1 U19.48 | length 1112.5
  Top Layer w10: U19.48@4926.18,2863.23 4947.85,2863.23 4948.76,2864.13 4948.76,2891.4 4967.36,2910 5106.16,2910 5159.86,2963.69 5368.98,2963.69 5400.05,2994.76 5400.05,3238.91 5519.21,3358.07 5519.21,3458.27 5545.71,3484.76 Q39.1@5563.5,3484.76
A1_NTC0: C174.1 R163.2 U22.5 | length 416.3
  Top Layer w8: R163.2@4056.77,3462.76 4056.77,3400 4056.77,3396.06 4087.36,3365.47 4087.36,3200 4113.54,3173.82 U22.5@4217.36,3173.82
A1_NTC0_C: D13.1 J11.1 R162.2 R163.1 | length 597.6
  Top Layer w8: R163.1@4056.77,3510 4056.77,3557.46 4156.77,3657.46 J11.1@4156.77,3700.39
  Bottom Layer w8: R162.2@4051.77,3405 4051.77,3405.98 4027.76,3430 4027.76,3485.39 4037.92,3495.55 4049.87,3495.55 4051.77,3497.46 4051.77,3499.92 4051.77,3595.39 J11.1@4156.77,3700.39
A1_NTC1: C176.1 R169.2 U22.4 | length 379
  Top Layer w8: C176.1@4132.99,3400 4125.18,3392.19 4125.18,3386.65 4102.36,3363.83 4102.36,3220 4122.95,3199.41 U22.4@4217.36,3199.41 ; R169.2@4134.44,3462.76 4134.6,3462.59 C176.1@4134.6,3400
A1_NTC1_C: D15.1 J11.2 R168.2 R169.1 | length 332.2
  Top Layer w8: R169.1@4134.44,3510 4134.44,3513.94 4156.77,3536.27 J11.2@4156.77,3599.61
  Bottom Layer w8: R168.2@4129.44,3405 4129.44,3405.98 4108.9,3426.53 4108.9,3496.83 4112.06,3499.99 4129.77,3499.99 4129.77,3565.93 4156.77,3592.93 J11.2@4156.77,3599.61
A1_NTC2: C178.1 R175.2 U22.2 | length 301.5
  Top Layer w8: U22.2@4193.36,3250.59 4152.05,3250.59 4147.36,3255.28 4147.36,3295 4182.36,3330 4182.36,3390 4192.36,3400 C178.1@4212.44,3400 ; R175.2@4212.1,3462.76 4212.44,3462.42 C178.1@4212.44,3400 ; U22.2@4212.5,3255.45 U22.2@4217.36,3250.59 ; C178.1@4212.77,3400 C178.1@4212.44,3400
A1_NTC2_C: D19.1 J11.3 R172.2 R175.1 | length 544.7
  Top Layer w8: R175.1@4212.1,3510 4212.1,3612.79 4256.77,3657.46 J11.3@4256.77,3700.39
  Bottom Layer w8: R172.2@4207.11,3405 4192.41,3419.7 4192.41,3444.95 4191.87,3445.5 4191.87,3487.9 4199.6,3495.63 4205.87,3495.63 4207.77,3497.54 4207.77,3500 4207.77,3651.39 4250.79,3694.41 4256.77,3694.41 J11.3@4256.77,3700.39
A1_NTC3: C181.1 R186.2 U22.1 | length 297.4
  Top Layer w8: U22.1@4217.36,3276.18 4312.68,3276.18 4317.36,3280.87 4317.36,3373.41 4302.52,3388.25 4298.58,3388.25 4290.77,3396.06 C181.1@4290.77,3400 ; R186.2@4289.77,3462.76 4290.27,3462.26 C181.1@4290.27,3400
A1_NTC3_C: D21.1 J11.4 R185.2 R186.1 | length 336.7
  Top Layer w8: J11.4@4256.77,3599.61 4256.77,3546.94 4289.77,3513.94 R186.1@4289.77,3510
  Bottom Layer w8: J11.4@4256.77,3599.61 4256.77,3531.46 4285.77,3502.46 4285.77,3500 4272.36,3500 4262.36,3490 4262.36,3428.41 4284.79,3405.98 R185.2@4284.79,3405
A1_NTC4: C183.1 R199.2 U22.15 | length 342.6
  Top Layer w8: R199.2@4367.44,3462.76 4368.1,3462.09 C183.1@4368.1,3396.73 ; C183.1@4368.77,3400 4368.77,3396.06 4360.96,3388.25 4342.05,3388.25 4337.36,3383.57 4337.36,3255.28 4342.05,3250.59 4423.09,3250.59 4427.95,3255.45 U22.15@4415.05,3255.45
A1_NTC4_C: D25.1 J11.7 R191.2 R199.1 | length 582.2
  Top Layer w8: R199.1@4367.44,3510 4367.44,3513.94 4410.86,3557.36 4410.86,3611.55 4456.77,3657.46 J11.7@4456.77,3700.39
  Bottom Layer w8: R191.2@4362.46,3405 4362.46,3405.98 4342.36,3426.08 4342.36,3482.4 4355.6,3495.63 4361.87,3495.63 4363.77,3497.54 4363.77,3500 4363.77,3502.46 4402.36,3541.05 4402.36,3603.05 4456.77,3657.46 J11.7@4456.77,3700.39
A1_NTC5: C185.1 R220.2 U22.14 | length 273.5
  Top Layer w8: C185.1@4444.99,3400 4444.99,3396.06 4423.34,3374.41 4423.34,3372.8 4423.18,3372.65 4423.18,3329.69 4466.66,3286.21 4466.66,3244.16 4452.36,3229.86 4447.24,3229.86 U22.14@4445.71,3228.33 ; R220.2@4445.1,3462.76 4445.94,3461.92 C185.1@4445.94,3400
A1_NTC5_C: D27.1 J11.8 R202.2 R220.1 | length 314.3
  Top Layer w8: R220.1@4445.1,3510 4445.1,3513.94 4456.77,3525.6 J11.8@4456.77,3599.61
  Bottom Layer w8: R202.2@4440.13,3405 4440.13,3405.98 4422.36,3423.75 4422.36,3484.4 4433.6,3495.64 4439.87,3495.64 4441.78,3497.54 4441.78,3500 4441.78,3502.46 4456.77,3517.46 J11.8@4456.77,3599.61
A1_NTC6: C187.1 R412.2 U22.13 | length 347.2
  Top Layer w8: U22.13@4445.71,3202.74 4447.24,3204.27 4452.36,3204.27 4480.66,3232.57 4480.66,3299.18 4501.48,3320 4533.72,3320 4552.36,3338.65 4552.36,3383.57 4547.68,3388.25 4532.58,3388.25 4524.77,3396.06 4524.77,3400 4523.77,3401 4523.77,3461.76 R412.2@4522.77,3462.76
A1_NTC6_C: D31.1 J11.9 R411.2 R412.1 | length 548.5
  Top Layer w8: R412.1@4522.77,3510 4515.87,3516.91 4515.87,3616.55 4556.77,3657.46 J11.9@4556.77,3700.39
  Bottom Layer w8: R411.2@4517.8,3405 4503.1,3419.7 4503.1,3429.26 4502.36,3430 4502.36,3486.4 4511.6,3495.63 4517.87,3495.63 4519.77,3497.54 4519.77,3500 4519.77,3502.46 4507.36,3514.87 4507.36,3615 4549.85,3657.49 4549.85,3693.47 J11.9@4556.77,3700.39
A1_NTC7: C189.1 R416.2 U22.12 | length 380
  Top Layer w8: U22.12@4445.71,3177.15 4447.24,3178.68 4452.36,3178.68 4497.36,3223.68 4497.36,3296.08 4506.28,3305 4552.36,3305 4572.36,3325 4572.36,3365.83 4593.18,3386.65 4593.18,3390.41 C189.1@4602.77,3400 ; R416.2@4600.44,3462.76 4601.6,3461.59 C189.1@4601.6,3401.17
A1_NTC7_C: D33.1 J11.10 R415.2 R416.1 | length 332.1
  Top Layer w8: J11.10@4556.77,3599.61 4557.67,3598.7 4557.67,3556.7 4600.44,3513.94 R416.1@4600.44,3510
  Bottom Layer w8: J11.10@4556.77,3599.61 4597.77,3558.61 4597.77,3500.01 4597.77,3497.55 4595.87,3495.64 4589.6,3495.64 4581.87,3487.91 4581.87,3416.4 R415.2@4591.77,3406.5
A1_NTC8: C173.1 R159.2 U23.5 | length 462.1
  Top Layer w8: R159.2@4678.44,3462.76 4680.1,3461.09 4680.1,3401.67 4686.77,3395 4686.77,3392.81 4689.58,3390 4702.68,3390 4707.36,3385.31 4707.36,3315 4714.77,3307.59 4818.61,3307.59 4823.3,3302.9 4823.3,3232.17 4834.06,3221.41 4834.06,3203.17 4860.17,3177.06 4885.97,3177.06 U23.5@4890.83,3172.2
A1_NTC8_C: D12.1 J11.13 R158.2 R159.1 | length 567.4
  Top Layer w8: R159.1@4678.44,3510 4678.44,3513.94 4715.87,3551.37 4715.87,3616.55 4756.77,3657.46 J11.13@4756.77,3700.39
  Bottom Layer w8: R158.2@4673.48,3405 4660.87,3417.62 4660.87,3488.82 4667.67,3495.62 4674.87,3495.62 4676.77,3497.52 4676.77,3499.99 4676.77,3525.59 4702.36,3551.18 4702.36,3603.05 4756.77,3657.46 J11.13@4756.77,3700.39
A1_NTC9: C175.1 R167.2 U23.4 | length 419.2
  Top Layer w8: R167.2@4758.1,3462.76 4759.44,3461.42 4759.44,3401.33 4760.77,3400 4760.77,3397.81 4752.96,3390 4752.96,3388.25 4737.05,3388.25 4732.36,3383.57 4732.36,3327.45 4738.22,3321.59 4825.77,3321.59 4837.3,3310.06 4837.3,3237.97 4851.1,3224.17 4851.1,3211.73 4860.17,3202.65 4885.97,3202.65 U23.4@4890.83,3197.8
A1_NTC9_C: D14.1 J11.14 R166.2 R167.1 | length 300.9
  Top Layer w8: J11.14@4756.77,3599.61 4757.44,3598.94 4757.44,3510.67 R167.1@4758.1,3510
  Bottom Layer w8: R166.2@4753.14,3405 4739.87,3418.27 4739.87,3487.9 4747.6,3495.63 4753.87,3495.63 4755.77,3497.53 4755.77,3499.99 4756.27,3500.49 4756.27,3599.11 J11.14@4756.77,3599.61
A1_NTC10: C177.1 R171.2 U23.2 | length 255.5
  Top Layer w8: R171.2@4834.36,3461.06 4835.86,3459.56 4835.86,3403.74 4837.36,3402.24 4837.36,3398.31 4859.17,3376.5 4859.17,3324.86 4851.3,3316.98 4851.3,3260.88 4858.35,3253.83 4883.33,3253.83 U23.2@4888.19,3248.98
A1_NTC10_C: D18.1 J11.15 R170.2 R171.1 | length 552.3
  Top Layer w8: R171.1@4834.36,3512.24 4834.36,3516.18 4815.87,3534.68 4815.87,3616.55 4856.77,3657.46 J11.15@4856.77,3700.39
  Bottom Layer w8: R170.2@4829.4,3407.24 4816.46,3420.19 4816.46,3490.15 4824.19,3497.88 4830.46,3497.88 4832.36,3499.78 4832.36,3502.24 4832.36,3504.7 4807.36,3529.7 4807.36,3610 4854.85,3657.49 4854.85,3698.47 J11.15@4856.77,3700.39
A1_NTC11: C180.1 R184.2 U23.1 | length 199.2
  Top Layer w8: U23.1@4893.41,3274.78 4893.41,3276.71 4890.69,3279.43 4890.69,3372.16 4897.04,3378.5 4897.21,3378.5 4905.18,3386.47 4905.18,3394.08 4912.94,3401.83 4912.94,3460.92 R184.2@4911.1,3462.76
A1_NTC11_C: D20.1 J11.16 R178.2 R184.1 | length 344
  Top Layer w8: J11.16@4856.77,3599.61 4867.07,3589.31 4867.07,3557.97 4911.1,3513.94 R184.1@4911.1,3510
  Bottom Layer w8: J11.16@4856.77,3599.61 4856.77,3555.46 4909.77,3502.46 4909.77,3500 4909.77,3497.54 4907.87,3495.63 4901.6,3495.63 4893.87,3487.9 4893.87,3417.29 R178.2@4906.15,3405
A1_NTC12: C182.1 R190.2 U23.15 | length 310.2
  Top Layer w8: R190.2@4988.77,3462.76 4990.77,3460.76 4990.77,3402 4992.77,3400 4992.77,3396.06 5023.23,3365.6 5023.23,3276.48 5050.74,3248.98 U23.15@5121.54,3248.98
A1_NTC12_C: D24.1 J11.19 R187.2 R190.1 | length 558.5
  Top Layer w8: R190.1@4988.77,3510 4988.77,3513.94 5015.87,3541.03 5015.87,3616.55 5056.77,3657.46 J11.19@5056.77,3700.39
  Bottom Layer w8: R187.2@4983.82,3405 4970.98,3417.84 4970.98,3487.02 4979.6,3495.63 4985.87,3495.63 4987.77,3497.54 4987.77,3500 4987.77,3502.46 5002.36,3517.05 5002.36,3645.98 J11.19@5056.77,3700.39
A1_NTC13: C184.1 R201.2 U23.14 | length 393.5
  Top Layer w8: R201.2@5066.44,3462.76 5068.6,3460.59 5068.6,3402.17 5061.18,3394.74 5061.18,3386.47 5053.21,3378.5 5053.04,3378.5 5045,3370.47 5045,3312.36 5060.11,3297.25 5157.33,3297.25 5169.36,3285.22 5169.36,3245.42 5152.19,3228.24 5126.39,3228.24 U23.14@5121.54,3223.39
A1_NTC13_C: D26.1 J11.20 R200.2 R201.1 | length 312.1
  Top Layer w8: J11.20@5056.77,3599.61 5056.77,3523.6 5066.44,3513.94 R201.1@5066.44,3510
  Bottom Layer w8: J11.20@5056.77,3599.61 5056.77,3511.47 5065.77,3502.47 5065.77,3500.01 5065.77,3497.55 5063.87,3495.64 5052.19,3495.64 5047.5,3490.96 5047.5,3418.99 R200.2@5061.5,3405
A1_NTC14: C186.1 R282.2 U23.13 | length 334.2
  Top Layer w8: U23.13@5121.54,3197.8 5178.68,3197.8 5183.36,3202.48 5183.36,3332.65 5183.58,3332.87 5183.58,3374.25 5161.77,3396.06 C186.1@5161.77,3400 ; R282.2@5156.77,3462.76 5159.27,3460.26 C186.1@5159.27,3400
A1_NTC14_C: D30.1 J11.21 R223.2 R282.1 | length 576.5
  Top Layer w8: R282.1@5156.77,3510 5156.77,3541.76 5115.87,3582.66 5115.87,3616.55 5156.77,3657.46 J11.21@5156.77,3700.39
  Bottom Layer w8: R223.2@5151.84,3405 5140.87,3415.97 5140.87,3487.9 5148.6,3495.63 5154.87,3495.63 5156.77,3497.54 5156.77,3500 5156.77,3502.46 5132.05,3527.18 5130.18,3527.18 5107.36,3550 5107.36,3650.98 J11.21@5156.77,3700.39
A1_NTC15: C188.1 R414.2 U23.12 | length 424.7
  Top Layer w8: U23.12@5121.54,3172.2 5184.57,3172.2 5197.36,3185 5197.36,3326.85 5197.58,3327.07 5197.58,3378.45 5197.36,3378.67 5197.36,3395.31 5202.05,3400 5263.77,3400 5261.44,3402.33 5261.44,3460.42 R414.2@5259.1,3462.76
A1_NTC15_C: D32.1 J11.22 R413.2 R414.1 | length 416
  Top Layer w8: J11.22@5156.77,3599.61 5234.63,3521.75 5251.29,3521.75 5259.1,3513.94 R414.1@5259.1,3510
  Bottom Layer w8: J11.22@5156.77,3599.61 5195.7,3560.68 5215.94,3560.68 5259.14,3517.47 D32.1@5259.14,3500 5259.14,3499.92 5257.24,3498.02 5241.24,3498.02 5237.36,3494.14 5237.36,3452.59 5239.47,3450.49 5239.47,3419.7 R413.2@5254.17,3405
A1_PULLUP: R158.1 R162.1 R166.1 R168.1 R170.1 R172.1 R178.1 R185.1 R187.1 R191.1 R195.2 R200.1 R202.1 R223.1 R411.1 R413.1 R415.1 | length 1377.6
  Top Layer w10: v2(5302.36,3335) 5320.12,3317.24 R195.2@5320.12,3295
  Bottom Layer w10: R162.1@4051.77,3342.01 R168.1@4127.08,3342.01 R172.1@4204.75,3342.01 4204.75,3341.02 4218.45,3327.32 4221.99,3327.32 4224.31,3325 4262.86,3325 4265.19,3327.32 4268.72,3327.32 4282.42,3341.02 R185.1@4282.42,3342.01 R191.1@4360.09,3342.01 R202.1@4437.77,3342.01 4437.77,3341.02 4451.47,3327.32 4455,3327.32 4457.32,3325 4495.88,3325 4498.2,3327.32 4501.74,3327.32 4515.44,3341.02 R411.1@4515.44,3342.01 R415.1@4589.41,3342.01 ; R415.1@4589.41,3343.5 4597.91,3335 4664.11,3335 R158.1@4671.12,3342.01 4753.14,3342.01 4764.4,3330.75 4818.15,3330.75 4829.4,3342.01 R178.1@4903.79,3342.01 4903.79,3341.02 4917.49,3327.32 4921.03,3327.32 4923.35,3325 4961.9,3325 4964.23,3327.32 4967.76,3327.32 4981.46,3341.02 R187.1@4981.46,3342.01 R200.1@5059.13,3342.01 5059.13,3341.02 5072.83,3327.32 5076.37,3327.32 5078.69,3325 5129.92,3325 5132.24,3327.32 5135.77,3327.32 5149.48,3341.02 R223.1@5149.48,3342.01 R413.1@5251.8,3342.01 5292.11,3342.01 5299.11,3335 v2(5302.36,3335)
